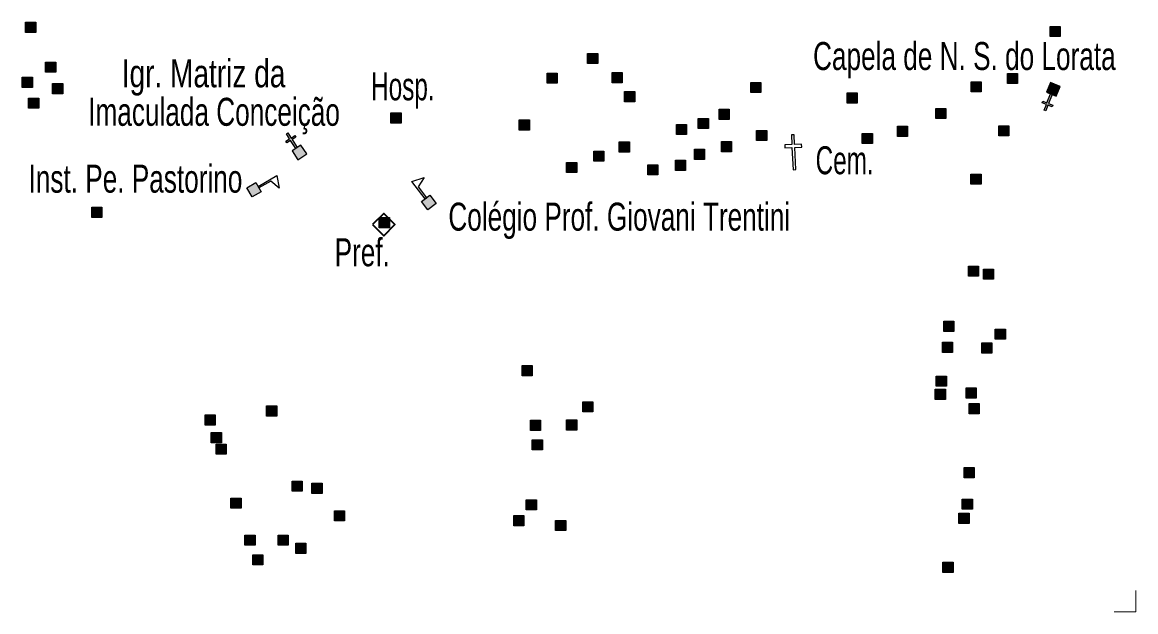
# Model space of a CAD drawing. Extents: x 649.2 to 674.4, y 7040 to 7068.1.
# Drawn here: x 670.84 to 674.026, y 7040.047 to 7041.732 of the extents above; entities that cross this region are included whole.
import ezdxf
from ezdxf.enums import TextEntityAlignment as Align

# ---------------------------------------------------------------- set-up
doc = ezdxf.new("R2010")
doc.units = 0
doc.header["$LTSCALE"] = 0.032
doc.header["$PDMODE"] = 32
doc.header["$PDSIZE"] = 0.016
for name, color, linetype, lineweight in [('2', 7, 'Continuous', 25), ('20', 7, 'Continuous', 25), ('4', 7, 'Continuous', 25), ('6', 7, 'Continuous', 25), ('63', 7, 'Continuous', 13)]:
    doc.layers.add(name, color=color, linetype=linetype, lineweight=lineweight)
doc.layers.add('61', color=7, linetype='Continuous')

msp = doc.modelspace()

# ---------------------------------------------------------------- hatches: boundary and pattern name
at = {"layer": '2'}
for points in [[(670.8496, 7041.7321), (670.8786, 7041.7321), (670.8786, 7041.7031), (670.8496, 7041.7031)], [(673.7811, 7041.7204), (673.8101, 7041.7204), (673.8101, 7041.6914), (673.7811, 7041.6914)], [(672.4575, 7041.6433), (672.4865, 7041.6433), (672.4865, 7041.6143), (672.4575, 7041.6143)], [(670.9068, 7041.6183), (670.9358, 7041.6183), (670.9358, 7041.5893), (670.9068, 7041.5893)], [(670.8399, 7041.5749), (670.8689, 7041.5749), (670.8689, 7041.5459), (670.8399, 7041.5459)], [(672.3415, 7041.5866), (672.3705, 7041.5866), (672.3705, 7041.5576), (672.3415, 7041.5576)], [(672.5278, 7041.5882), (672.5568, 7041.5882), (672.5568, 7041.5592), (672.5278, 7041.5592)], [(673.659, 7041.5857), (673.688, 7041.5857), (673.688, 7041.5567), (673.659, 7041.5567)], [(670.9268, 7041.5569), (670.9558, 7041.5569), (670.9558, 7041.5279), (670.9268, 7041.5279)], [(672.9242, 7041.5603), (672.9532, 7041.5603), (672.9532, 7041.5313), (672.9242, 7041.5313)], [(673.5551, 7041.5622), (673.5841, 7041.5622), (673.5841, 7041.5332), (673.5551, 7041.5332)], [(670.8579, 7041.5155), (670.8869, 7041.5155), (670.8869, 7041.4865), (670.8579, 7041.4865)], [(672.5634, 7041.534), (672.5924, 7041.534), (672.5924, 7041.505), (672.5634, 7041.505)], [(673.2002, 7041.5301), (673.2292, 7041.5301), (673.2292, 7041.5011), (673.2002, 7041.5011)], [(672.8336, 7041.4832), (672.8626, 7041.4832), (672.8626, 7041.4542), (672.8336, 7041.4542)], [(673.4537, 7041.4857), (673.4827, 7041.4857), (673.4827, 7041.4567), (673.4537, 7041.4567)], [(671.8948, 7041.4728), (671.9238, 7041.4728), (671.9238, 7041.4438), (671.8948, 7041.4438)], [(672.2619, 7041.4527), (672.2909, 7041.4527), (672.2909, 7041.4237), (672.2619, 7041.4237)], [(672.7743, 7041.457), (672.8033, 7041.457), (672.8033, 7041.428), (672.7743, 7041.428)], [(672.7116, 7041.44), (672.7406, 7041.44), (672.7406, 7041.411), (672.7116, 7041.411)], [(672.9412, 7041.4231), (672.9702, 7041.4231), (672.9702, 7041.3941), (672.9412, 7041.3941)], [(673.2433, 7041.4145), (673.2723, 7041.4145), (673.2723, 7041.3855), (673.2433, 7041.3855)], [(673.3441, 7041.4346), (673.3731, 7041.4346), (673.3731, 7041.4056), (673.3441, 7041.4056)], [(673.6338, 7041.436), (673.6628, 7041.436), (673.6628, 7041.407), (673.6338, 7041.407)], [(672.5482, 7041.39), (672.5772, 7041.39), (672.5772, 7041.361), (672.5482, 7041.361)], [(672.8404, 7041.3909), (672.8694, 7041.3909), (672.8694, 7041.3619), (672.8404, 7041.3619)], [(672.4753, 7041.3638), (672.5043, 7041.3638), (672.5043, 7041.3348), (672.4753, 7041.3348)], [(672.7633, 7041.3689), (672.7923, 7041.3689), (672.7923, 7041.3399), (672.7633, 7041.3399)], [(672.3974, 7041.3316), (672.4264, 7041.3316), (672.4264, 7041.3026), (672.3974, 7041.3026)], [(672.6295, 7041.3248), (672.6585, 7041.3248), (672.6585, 7041.2958), (672.6295, 7041.2958)], [(672.7091, 7041.3375), (672.7381, 7041.3375), (672.7381, 7041.3085), (672.7091, 7041.3085)], [(673.5545, 7041.2982), (673.5835, 7041.2982), (673.5835, 7041.2692), (673.5545, 7041.2692)], [(671.0385, 7041.2031), (671.0675, 7041.2031), (671.0675, 7041.1741), (671.0385, 7041.1741)], [(671.8614, 7041.1737), (671.8904, 7041.1737), (671.8904, 7041.1447), (671.8614, 7041.1447)], [(673.547, 7041.035), (673.576, 7041.035), (673.576, 7041.006), (673.547, 7041.006)], [(673.5902, 7041.0265), (673.6192, 7041.0265), (673.6192, 7040.9975), (673.5902, 7040.9975)], [(673.4766, 7040.8773), (673.5056, 7040.8773), (673.5056, 7040.8483), (673.4766, 7040.8483)], [(673.624, 7040.8547), (673.653, 7040.8547), (673.653, 7040.8257), (673.624, 7040.8257)], [(673.4729, 7040.8172), (673.5019, 7040.8172), (673.5019, 7040.7882), (673.4729, 7040.7882)], [(673.5855, 7040.8153), (673.6145, 7040.8153), (673.6145, 7040.7863), (673.5855, 7040.7863)], [(672.2702, 7040.7504), (672.2992, 7040.7504), (672.2992, 7040.7214), (672.2702, 7040.7214)], [(673.455, 7040.7205), (673.484, 7040.7205), (673.484, 7040.6915), (673.455, 7040.6915)], [(673.4522, 7040.6829), (673.4812, 7040.6829), (673.4812, 7040.6539), (673.4522, 7040.6539)], [(673.5405, 7040.6867), (673.5695, 7040.6867), (673.5695, 7040.6577), (673.5405, 7040.6577)], [(672.4437, 7040.647), (672.4727, 7040.647), (672.4727, 7040.618), (672.4437, 7040.618)], [(671.5392, 7040.6351), (671.5682, 7040.6351), (671.5682, 7040.6061), (671.5392, 7040.6061)], [(673.5489, 7040.6416), (673.5779, 7040.6416), (673.5779, 7040.6126), (673.5489, 7040.6126)], [(671.3629, 7040.6092), (671.3919, 7040.6092), (671.3919, 7040.5802), (671.3629, 7040.5802)], [(672.2939, 7040.5942), (672.3229, 7040.5942), (672.3229, 7040.5652), (672.2939, 7040.5652)], [(672.3974, 7040.5952), (672.4264, 7040.5952), (672.4264, 7040.5662), (672.3974, 7040.5662)], [(671.3805, 7040.5587), (671.4095, 7040.5587), (671.4095, 7040.5297), (671.3805, 7040.5297)], [(671.3946, 7040.5257), (671.4236, 7040.5257), (671.4236, 7040.4967), (671.3946, 7040.4967)], [(672.2993, 7040.5381), (672.3283, 7040.5381), (672.3283, 7040.5091), (672.2993, 7040.5091)], [(673.5348, 7040.4587), (673.5638, 7040.4587), (673.5638, 7040.4297), (673.5348, 7040.4297)], [(671.6121, 7040.4199), (671.6411, 7040.4199), (671.6411, 7040.3909), (671.6121, 7040.3909)], [(671.6686, 7040.414), (671.6976, 7040.414), (671.6976, 7040.385), (671.6686, 7040.385)], [(671.4369, 7040.3717), (671.4659, 7040.3717), (671.4659, 7040.3427), (671.4369, 7040.3427)], [(672.2821, 7040.3667), (672.3111, 7040.3667), (672.3111, 7040.3377), (672.2821, 7040.3377)], [(673.5294, 7040.3686), (673.5584, 7040.3686), (673.5584, 7040.3396), (673.5294, 7040.3396)], [(671.7332, 7040.3353), (671.7622, 7040.3353), (671.7622, 7040.3063), (671.7332, 7040.3063)], [(673.52, 7040.3283), (673.549, 7040.3283), (673.549, 7040.2993), (673.52, 7040.2993)], [(672.2465, 7040.3214), (672.2755, 7040.3214), (672.2755, 7040.2924), (672.2465, 7040.2924)], [(672.3661, 7040.3074), (672.3951, 7040.3074), (672.3951, 7040.2784), (672.3661, 7040.2784)], [(671.4769, 7040.2659), (671.5059, 7040.2659), (671.5059, 7040.2369), (671.4769, 7040.2369)], [(671.5722, 7040.2659), (671.6012, 7040.2659), (671.6012, 7040.2369), (671.5722, 7040.2369)], [(671.6227, 7040.2424), (671.6517, 7040.2424), (671.6517, 7040.2134), (671.6227, 7040.2134)], [(671.4993, 7040.2095), (671.5283, 7040.2095), (671.5283, 7040.1805), (671.4993, 7040.1805)], [(673.4741, 7040.1882), (673.5031, 7040.1882), (673.5031, 7040.1592), (673.4741, 7040.1592)]]:
    msp.add_hatch(color=256, dxfattribs=at).paths.add_polyline_path(points)
at = {"layer": '4'}
for points in [[(671.4824, 7041.2584), (671.5083, 7041.2735), (671.5234, 7041.2475), (671.4974, 7041.2325)], [(672.0005, 7041.1957), (671.9825, 7041.2196), (672.0064, 7041.2377), (672.0245, 7041.2137)]]:
    msp.add_hatch(color=256, dxfattribs=at).paths.add_polyline_path(points)
at = {"layer": '6'}
for points in [[(673.7986, 7041.5207), (673.8098, 7041.5486), (673.782, 7041.5598), (673.7707, 7041.532)], [(673.7823, 7041.5273), (673.787, 7041.5254), (673.7767, 7041.4999), (673.7883, 7041.4953), (673.7864, 7041.4906), (673.7748, 7041.4953), (673.7682, 7041.4791), (673.7636, 7041.4809), (673.7702, 7041.4972), (673.7586, 7041.5019), (673.7604, 7041.5065), (673.772, 7041.5018)], [(671.6269, 7041.3739), (671.6227, 7041.3712), (671.6077, 7041.3943), (671.5972, 7041.3875), (671.5945, 7041.3917), (671.605, 7041.3985), (671.5955, 7041.4132), (671.5997, 7041.4159), (671.6092, 7041.4012), (671.6197, 7041.408), (671.6224, 7041.4038), (671.6119, 7041.397)], [(671.6122, 7041.3644), (671.6285, 7041.3392), (671.6537, 7041.3556), (671.6374, 7041.3807)]]:
    msp.add_hatch(color=256, dxfattribs=at).paths.add_polyline_path(points)

# ---------------------------------------------------------------- linework, layer by layer
at = {"layer": '2'}
for points in [[(670.8496, 7041.7321), (670.8786, 7041.7321), (670.8786, 7041.7031), (670.8496, 7041.7031)], [(673.7811, 7041.7204), (673.8101, 7041.7204), (673.8101, 7041.6914), (673.7811, 7041.6914)], [(672.4575, 7041.6433), (672.4865, 7041.6433), (672.4865, 7041.6143), (672.4575, 7041.6143)], [(670.9068, 7041.6183), (670.9358, 7041.6183), (670.9358, 7041.5893), (670.9068, 7041.5893)], [(670.8399, 7041.5749), (670.8689, 7041.5749), (670.8689, 7041.5459), (670.8399, 7041.5459)], [(672.3415, 7041.5866), (672.3705, 7041.5866), (672.3705, 7041.5576), (672.3415, 7041.5576)], [(672.5278, 7041.5882), (672.5568, 7041.5882), (672.5568, 7041.5592), (672.5278, 7041.5592)], [(673.659, 7041.5857), (673.688, 7041.5857), (673.688, 7041.5567), (673.659, 7041.5567)], [(670.9268, 7041.5569), (670.9558, 7041.5569), (670.9558, 7041.5279), (670.9268, 7041.5279)], [(672.9242, 7041.5603), (672.9532, 7041.5603), (672.9532, 7041.5313), (672.9242, 7041.5313)], [(673.5551, 7041.5622), (673.5841, 7041.5622), (673.5841, 7041.5332), (673.5551, 7041.5332)], [(670.8579, 7041.5155), (670.8869, 7041.5155), (670.8869, 7041.4865), (670.8579, 7041.4865)], [(672.5634, 7041.534), (672.5924, 7041.534), (672.5924, 7041.505), (672.5634, 7041.505)], [(673.2002, 7041.5301), (673.2292, 7041.5301), (673.2292, 7041.5011), (673.2002, 7041.5011)], [(672.8336, 7041.4832), (672.8626, 7041.4832), (672.8626, 7041.4542), (672.8336, 7041.4542)], [(673.4537, 7041.4857), (673.4827, 7041.4857), (673.4827, 7041.4567), (673.4537, 7041.4567)], [(671.8948, 7041.4728), (671.9238, 7041.4728), (671.9238, 7041.4438), (671.8948, 7041.4438)], [(672.2619, 7041.4527), (672.2909, 7041.4527), (672.2909, 7041.4237), (672.2619, 7041.4237)], [(672.7743, 7041.457), (672.8033, 7041.457), (672.8033, 7041.428), (672.7743, 7041.428)], [(672.7116, 7041.44), (672.7406, 7041.44), (672.7406, 7041.411), (672.7116, 7041.411)], [(672.9412, 7041.4231), (672.9702, 7041.4231), (672.9702, 7041.3941), (672.9412, 7041.3941)], [(673.2433, 7041.4145), (673.2723, 7041.4145), (673.2723, 7041.3855), (673.2433, 7041.3855)], [(673.3441, 7041.4346), (673.3731, 7041.4346), (673.3731, 7041.4056), (673.3441, 7041.4056)], [(673.6338, 7041.436), (673.6628, 7041.436), (673.6628, 7041.407), (673.6338, 7041.407)], [(672.5482, 7041.39), (672.5772, 7041.39), (672.5772, 7041.361), (672.5482, 7041.361)], [(672.8404, 7041.3909), (672.8694, 7041.3909), (672.8694, 7041.3619), (672.8404, 7041.3619)], [(672.4753, 7041.3638), (672.5043, 7041.3638), (672.5043, 7041.3348), (672.4753, 7041.3348)], [(672.7633, 7041.3689), (672.7923, 7041.3689), (672.7923, 7041.3399), (672.7633, 7041.3399)], [(672.3974, 7041.3316), (672.4264, 7041.3316), (672.4264, 7041.3026), (672.3974, 7041.3026)], [(672.6295, 7041.3248), (672.6585, 7041.3248), (672.6585, 7041.2958), (672.6295, 7041.2958)], [(672.7091, 7041.3375), (672.7381, 7041.3375), (672.7381, 7041.3085), (672.7091, 7041.3085)], [(673.5545, 7041.2982), (673.5835, 7041.2982), (673.5835, 7041.2692), (673.5545, 7041.2692)], [(671.0385, 7041.2031), (671.0675, 7041.2031), (671.0675, 7041.1741), (671.0385, 7041.1741)], [(671.8614, 7041.1737), (671.8904, 7041.1737), (671.8904, 7041.1447), (671.8614, 7041.1447)], [(673.547, 7041.035), (673.576, 7041.035), (673.576, 7041.006), (673.547, 7041.006)], [(673.5902, 7041.0265), (673.6192, 7041.0265), (673.6192, 7040.9975), (673.5902, 7040.9975)], [(673.4766, 7040.8773), (673.5056, 7040.8773), (673.5056, 7040.8483), (673.4766, 7040.8483)], [(673.624, 7040.8547), (673.653, 7040.8547), (673.653, 7040.8257), (673.624, 7040.8257)], [(673.4729, 7040.8172), (673.5019, 7040.8172), (673.5019, 7040.7882), (673.4729, 7040.7882)], [(673.5855, 7040.8153), (673.6145, 7040.8153), (673.6145, 7040.7863), (673.5855, 7040.7863)], [(672.2702, 7040.7504), (672.2992, 7040.7504), (672.2992, 7040.7214), (672.2702, 7040.7214)], [(673.455, 7040.7205), (673.484, 7040.7205), (673.484, 7040.6915), (673.455, 7040.6915)], [(673.4522, 7040.6829), (673.4812, 7040.6829), (673.4812, 7040.6539), (673.4522, 7040.6539)], [(673.5405, 7040.6867), (673.5695, 7040.6867), (673.5695, 7040.6577), (673.5405, 7040.6577)], [(672.4437, 7040.647), (672.4727, 7040.647), (672.4727, 7040.618), (672.4437, 7040.618)], [(671.5392, 7040.6351), (671.5682, 7040.6351), (671.5682, 7040.6061), (671.5392, 7040.6061)], [(673.5489, 7040.6416), (673.5779, 7040.6416), (673.5779, 7040.6126), (673.5489, 7040.6126)], [(671.3629, 7040.6092), (671.3919, 7040.6092), (671.3919, 7040.5802), (671.3629, 7040.5802)], [(672.2939, 7040.5942), (672.3229, 7040.5942), (672.3229, 7040.5652), (672.2939, 7040.5652)], [(672.3974, 7040.5952), (672.4264, 7040.5952), (672.4264, 7040.5662), (672.3974, 7040.5662)], [(671.3805, 7040.5587), (671.4095, 7040.5587), (671.4095, 7040.5297), (671.3805, 7040.5297)], [(671.3946, 7040.5257), (671.4236, 7040.5257), (671.4236, 7040.4967), (671.3946, 7040.4967)], [(672.2993, 7040.5381), (672.3283, 7040.5381), (672.3283, 7040.5091), (672.2993, 7040.5091)], [(673.5348, 7040.4587), (673.5638, 7040.4587), (673.5638, 7040.4297), (673.5348, 7040.4297)], [(671.6121, 7040.4199), (671.6411, 7040.4199), (671.6411, 7040.3909), (671.6121, 7040.3909)], [(671.6686, 7040.414), (671.6976, 7040.414), (671.6976, 7040.385), (671.6686, 7040.385)], [(671.4369, 7040.3717), (671.4659, 7040.3717), (671.4659, 7040.3427), (671.4369, 7040.3427)], [(672.2821, 7040.3667), (672.3111, 7040.3667), (672.3111, 7040.3377), (672.2821, 7040.3377)], [(673.5294, 7040.3686), (673.5584, 7040.3686), (673.5584, 7040.3396), (673.5294, 7040.3396)], [(671.7332, 7040.3353), (671.7622, 7040.3353), (671.7622, 7040.3063), (671.7332, 7040.3063)], [(673.52, 7040.3283), (673.549, 7040.3283), (673.549, 7040.2993), (673.52, 7040.2993)], [(672.2465, 7040.3214), (672.2755, 7040.3214), (672.2755, 7040.2924), (672.2465, 7040.2924)], [(672.3661, 7040.3074), (672.3951, 7040.3074), (672.3951, 7040.2784), (672.3661, 7040.2784)], [(671.4769, 7040.2659), (671.5059, 7040.2659), (671.5059, 7040.2369), (671.4769, 7040.2369)], [(671.5722, 7040.2659), (671.6012, 7040.2659), (671.6012, 7040.2369), (671.5722, 7040.2369)], [(671.6227, 7040.2424), (671.6517, 7040.2424), (671.6517, 7040.2134), (671.6227, 7040.2134)], [(671.4993, 7040.2095), (671.5283, 7040.2095), (671.5283, 7040.1805), (671.4993, 7040.1805)], [(673.4741, 7040.1882), (673.5031, 7040.1882), (673.5031, 7040.1592), (673.4741, 7040.1592)]]:
    msp.add_lwpolyline(points, close=True, dxfattribs=at)
at = {"layer": '2', "lineweight": 35}
msp.add_lwpolyline([(671.8424, 7041.1535), (671.8742, 7041.1217), (671.906, 7041.1535), (671.8742, 7041.1853)], close=True, dxfattribs=at)
at = {"layer": '2'}
msp.add_point((671.8742, 7041.1535), dxfattribs=at)
at = {"layer": '20'}
for points in [[(673.0499, 7041.3826), (673.0485, 7041.4106), (673.0405, 7041.4102), (673.0419, 7041.3822)], [(673.0419, 7041.3822), (673.0219, 7041.3813), (673.0223, 7041.3728), (673.0423, 7041.3738), (673.0454, 7041.3103)], [(673.0503, 7041.3741), (673.0703, 7041.3751), (673.0698, 7041.3836), (673.0499, 7041.3826)], [(673.0454, 7041.3103), (673.0533, 7041.3107), (673.0503, 7041.3741)]]:
    msp.add_lwpolyline(points, dxfattribs=at)
at = {"layer": '4'}
for p, q in [((671.5146, 7041.2627), (671.5171, 7041.2583)), ((671.9924, 7041.2271), (671.9964, 7041.2301))]:
    msp.add_line(p, q, dxfattribs=at)
for points in [[(671.5146, 7041.2627), (671.5686, 7041.294), (671.5754, 7041.2574), (671.5513, 7041.2781), (671.5171, 7041.2583)], [(671.9924, 7041.2271), (671.9548, 7041.277), (671.9903, 7041.2881), (671.9726, 7041.2617), (671.9964, 7041.2301)], [(671.4824, 7041.2584), (671.5083, 7041.2735), (671.5234, 7041.2475), (671.4974, 7041.2325)], [(672.0005, 7041.1957), (671.9825, 7041.2196), (672.0064, 7041.2377), (672.0245, 7041.2137)]]:
    msp.add_lwpolyline(points, close=True, dxfattribs=at)
at = {"layer": '6'}
for points in [[(673.7986, 7041.5207), (673.8098, 7041.5486), (673.782, 7041.5598), (673.7707, 7041.532)], [(673.7823, 7041.5273), (673.787, 7041.5254), (673.7767, 7041.4999), (673.7883, 7041.4953), (673.7864, 7041.4906), (673.7748, 7041.4953), (673.7682, 7041.4791), (673.7636, 7041.4809), (673.7702, 7041.4972), (673.7586, 7041.5019), (673.7604, 7041.5065), (673.772, 7041.5018)], [(671.6269, 7041.3739), (671.6227, 7041.3712), (671.6077, 7041.3943), (671.5972, 7041.3875), (671.5945, 7041.3917), (671.605, 7041.3985), (671.5955, 7041.4132), (671.5997, 7041.4159), (671.6092, 7041.4012), (671.6197, 7041.408), (671.6224, 7041.4038), (671.6119, 7041.397)], [(671.6122, 7041.3644), (671.6285, 7041.3392), (671.6537, 7041.3556), (671.6374, 7041.3807)]]:
    msp.add_lwpolyline(points, close=True, dxfattribs=at)
at = {"layer": '63'}
msp.add_lwpolyline([(673.9643, 7040.0466), (674.0259, 7040.0466), (674.0259, 7040.1073)], dxfattribs=at)

# ---------------------------------------------------------------- texts
at = {"layer": '61'}
for s, width, p in [('Capela de N. S. do Lorata', 0.7, (673.9685, 7041.5956)), ('  Igr. Matriz da       ', 0.75, (671.7488, 7041.5461)), ('Imaculada Conceição', 0.7, (671.7488, 7041.4361)), ('Inst. Pe. Pastorino', 0.7, (671.4697, 7041.2449))]:
    msp.add_text(s, height=0.08, dxfattribs=dict(at, width=width)).set_placement(p, align=Align.RIGHT)
for s, width, p in [('Hosp.', 0.65, (671.8382, 7041.509)), ('Cem.', 0.65, (673.1099, 7041.2976)), ('Colégio Prof. Giovani Trentini', 0.7, (672.0591, 7041.1363)), ('Pref.', 0.7, (671.7336, 7041.0344))]:
    msp.add_text(s, height=0.08, dxfattribs=dict(at, width=width)).set_placement(p)

doc.saveas('drawing.dxf')
